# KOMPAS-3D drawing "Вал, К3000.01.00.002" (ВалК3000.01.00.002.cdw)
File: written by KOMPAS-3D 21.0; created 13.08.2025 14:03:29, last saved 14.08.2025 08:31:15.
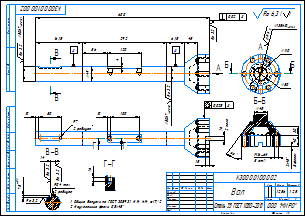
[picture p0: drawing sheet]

Sheet 1: A3, landscape

Document properties: Автор: admin; Знак неуказанной шероховатости: 4; Параметр неуказанной шероховатости: Ra 6,3; Масса: 12.558835

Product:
- Part/product: Вал  | designation К3000.01.00.002
    Материал: Сталь 35 ГОСТ 1050-2013 (density 7826 kg/m3)
    Масса: 12.558835

Title block, sheet 1: Наименование: Вал; designation: К3000.01.00.002; Материал: Сталь 35 ГОСТ 1050-2013; Масса: 12,56; Количество листов документа: 1; organisation: ООО "МИРО"; Форматы листов документа: A3; stored path: C:\Users\ShavarinML\Desktop\Стапель\2D\ВалК3000.01.00.002.cdw

Views: Спереди 1, Спереди, Проекционный вид 2, Вид по стрелке 3, Разрез Б-Б, Разрез В-В, Разрез Г-Г, Вид по стрелке А, Вид:1
Referenced files in C:\Users\ShavarinML\Desktop\Стапель\Из трубы\: Вал.m3d
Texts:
  Ra 3,2
  max
  Ra 6,3
  Ra 6,3 ( )
  К3000.01.00.002 Вал
Dimensions and other numbers on the sheet: 49; 4; 120; 161,5; 292; 86; 61,5; 45; 50; 600; 0,02; 15; 10; 100; 16; 2 паза; 0,025; 80; 7; 2 радиуса; 135; 110; -6H; 8 отв.; 40; 2; 8 фасок; 30; 14; 0,4; 7,5; 1:2,5; 1; 12,56

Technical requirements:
  Общие допуски по ГОСТ 30893.1: H14, h14,   IT/2.
  Неуказанные фаски 0,5х45 .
